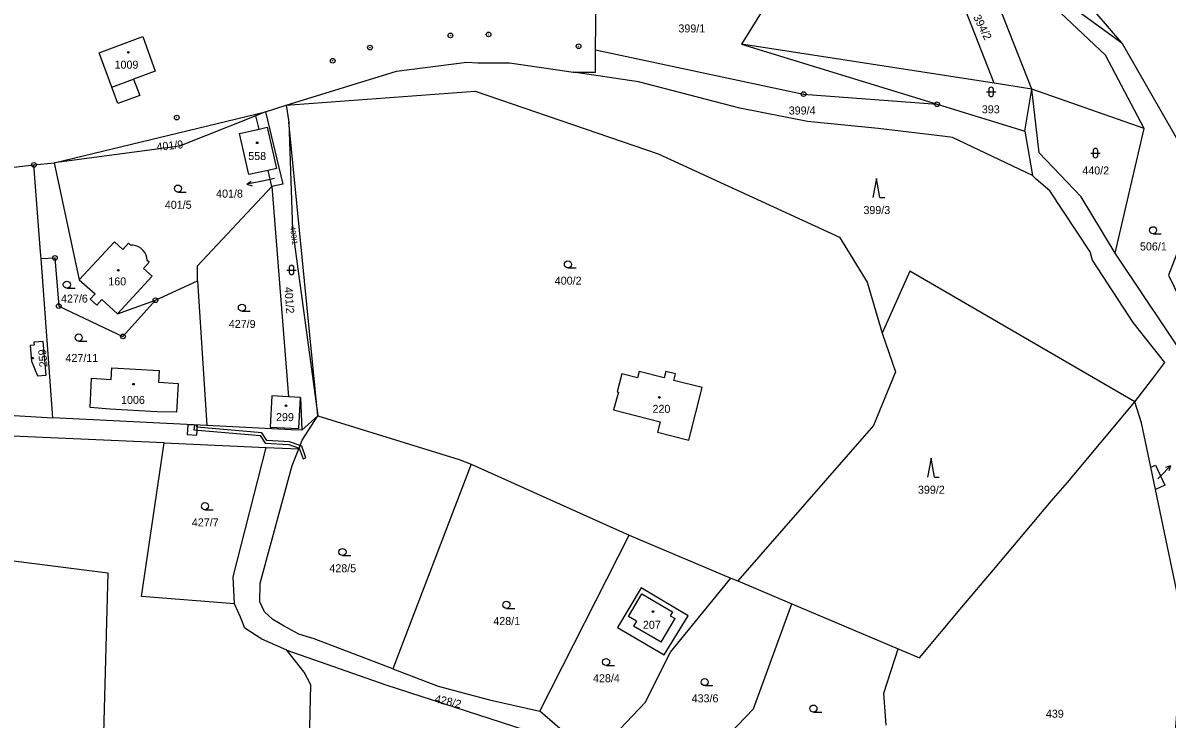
# Model space of a CAD drawing. Extents: x -725728 to -720881, y -1068679 to -1063504.
# Drawn here: x -723693.8 to -723450.7, y -1067427.1 to -1067279.2 of the extents above; entities that cross this region are included whole.
import ezdxf

# ---------------------------------------------------------------- set-up
doc = ezdxf.new("R2010")
doc.units = 0
for name, color, linetype in [('Hranice parcel', 7, 'Continuous'), ('Parcelní čísla', 7, 'Continuous'), ('Pop  PČ popisy', 7, 'Continuous'), ('Vnitřní kresba', 7, 'Continuous'), ('Věcná břemena k části', 7, 'Continuous'), ('Značky bodu BP', 7, 'Continuous'), ('Značky budov', 7, 'Continuous'), ('Značky kultur', 7, 'Continuous')]:
    doc.layers.add(name, color=color, linetype=linetype)

# ---------------------------------------------------------------- blocks, each defined once
blk = doc.blocks.new('4.02_4')
at = {"layer": 'Značky budov'}
blk.add_circle((-0.001, 0), 0.0175, dxfattribs=at)
blk = doc.blocks.new('4.02_3')
at = {"layer": 'Značky budov'}
blk.add_circle((-0.001, 0), 0.0175, dxfattribs=at)
blk = doc.blocks.new('1029_93')
at = {"layer": 'Pop  PČ popisy'}
for p, q in [((-0.293, -0.062), (-0.206, 0.007)), ((0, 0), (-0.293, -0.062)), ((-0.293, -0.062), (-0.185, -0.091))]:
    blk.add_line(p, q, dxfattribs=at)
blk = doc.blocks.new('1029_110')
at = {"layer": 'Pop  PČ popisy'}
for p, q in [((0, 0), (0.208, 0.216)), ((0.208, 0.216), (0.103, 0.179)), ((0.208, 0.216), (0.175, 0.109))]:
    blk.add_line(p, q, dxfattribs=at)
blk = doc.blocks.new('3.04_2')
at = {"layer": 'Značky kultur'}
blk.add_line((0.001, 0), (0.176, 0), dxfattribs=at)
blk.add_circle((0.001, 0.075), 0.075, dxfattribs=at)
blk = doc.blocks.new('3.16_2')
at = {"layer": 'Značky kultur'}
for p, q in [((-0.1, 0.1), (0.1, 0.1)), ((-0.05, 0.15), (-0.05, 0.05)), ((0.05, 0.05), (0.05, 0.15))]:
    blk.add_line(p, q, dxfattribs=at)
for centre, start, end in [((0, 0.15), 0, 180), ((0, 0.05), 180, 359.9879)]:
    blk.add_arc(centre, 0.05, start, end, dxfattribs=at)
blk = doc.blocks.new('3.04_3')
at = {"layer": 'Značky kultur'}
blk.add_line((0.001, 0), (0.176, 0), dxfattribs=at)
blk.add_circle((0.001, 0.075), 0.075, dxfattribs=at)
blk = doc.blocks.new('3.08_2')
at = {"layer": 'Značky kultur'}
for p, q in [((0, 0.4), (-0.075, 0)), ((0.075, 0), (0, 0.4)), ((0.075, 0), (0.175, 0))]:
    blk.add_line(p, q, dxfattribs=at)
blk = doc.blocks.new('3.08_1')
at = {"layer": 'Značky kultur'}
for p, q in [((0, 0.4), (-0.075, 0)), ((0.075, 0), (0, 0.4)), ((0.075, 0), (0.175, 0))]:
    blk.add_line(p, q, dxfattribs=at)
blk = doc.blocks.new('1.05_1')
at = {"layer": 'Značky bodu BP'}
for radius in [0.05, 0.00303]:
    blk.add_circle((0, 0), radius, dxfattribs=at)
blk = doc.blocks.new('1.05_2')
at = {"layer": 'Značky bodu BP'}
for radius in [0.05, 0.00303]:
    blk.add_circle((0, 0), radius, dxfattribs=at)

msp = doc.modelspace()

# ---------------------------------------------------------------- linework, layer by layer
at = {"layer": 'Hranice parcel'}
for p, q in [((-723572.12, -1067284.9), (-723571.84, -1067259.72)), ((-723460.32, -1067283.4), (-723469.08, -1067273.2)), ((-723536.24, -1067275.86), (-723541.11, -1067283.68)), ((-723541.11, -1067283.68), (-723499.61, -1067296.46)), ((-723487.5, -1067292), (-723541.11, -1067283.68)), ((-723479.48, -1067293.24), (-723487.5, -1067292)), ((-723480.98, -1067302.19), (-723479.48, -1067293.24)), ((-723455.59, -1067301.61), (-723479.48, -1067293.24)), ((-723642.24, -1067298.09), (-723637.82, -1067296.63)), ((-723637.82, -1067296.63), (-723637.28, -1067300.3)), ((-723499.61, -1067296.46), (-723480.98, -1067302.19)), ((-723687.12, -1067308.88), (-723642.24, -1067298.09)), ((-723642.24, -1067298.09), (-723644.27, -1067298.95)), ((-723643.59, -1067301.74), (-723644.27, -1067298.95)), ((-723631.1, -1067362.69), (-723637.28, -1067300.3)), ((-723480.98, -1067302.19), (-723479.34, -1067311.61)), ((-723461.74, -1067328.13), (-723455.59, -1067301.61)), ((-723691.4, -1067309.34), (-723687.12, -1067308.88)), ((-723687.12, -1067308.88), (-723681.82, -1067333.76)), ((-723640.9, -1067313.95), (-723641.66, -1067310.52)), ((-723640.9, -1067313.95), (-723637.32, -1067358.65)), ((-723436.8, -1067365.55), (-723461.74, -1067328.13)), ((-723687.41, -1067363.12), (-723689.89, -1067329.25)), ((-723665.61, -1067338.11), (-723656.68, -1067333.97)), ((-723656.68, -1067333.97), (-723654.7, -1067364.76)), ((-723673.63, -1067340.97), (-723665.61, -1067338.11)), ((-723634.8, -1067358.79), (-723637.32, -1067358.65)), ((-723634.8, -1067358.79), (-723634.54, -1067365.73)), ((-723722.85, -1067360.93), (-723687.41, -1067363.12)), ((-723634.54, -1067365.73), (-723631.1, -1067362.69)), ((-723663.72, -1067368.43), (-723739.93, -1067365.04)), ((-723654.7, -1067364.76), (-723687.41, -1067363.12)), ((-723663.72, -1067368.43), (-723642.12, -1067369.4)), ((-723642.12, -1067369.4), (-723635.16, -1067369.71)), ((-723598.56, -1067372.95), (-723615.22, -1067416.45)), ((-723598.56, -1067372.95), (-723564.97, -1067388.01)), ((-723453.2, -1067378.34), (-723454.19, -1067373.61)), ((-723564.97, -1067388.01), (-723543.39, -1067397.15)), ((-723543.39, -1067397.15), (-723541.92, -1067397.77)), ((-723541.92, -1067397.77), (-723530.41, -1067402.64)), ((-723530.41, -1067402.64), (-723507.89, -1067412.18))]:
    msp.add_line(p, q, dxfattribs=at)
for points in [[(-723487.5, -1067292), (-723497.56, -1067266.08), (-723536.73, -1067210.56)], [(-723479.48, -1067293.24), (-723487.12, -1067273.79), (-723514.57, -1067234.97)], [(-723455.59, -1067301.61), (-723463.81, -1067286.04), (-723487.72, -1067263.42), (-723460.32, -1067283.4)], [(-723668.3, -1067282.09), (-723665.63, -1067289.4), (-723670.25, -1067291.11), (-723668.94, -1067294.62), (-723673.58, -1067296.33), (-723674.88, -1067292.82), (-723677.57, -1067285.52), (-723668.3, -1067282.09)], [(-723576.81, -1067289.67), (-723572.17, -1067289.67), (-723572.12, -1067284.9)], [(-723572.12, -1067284.9), (-723527.95, -1067294.31), (-723499.61, -1067296.46)], [(-723460.32, -1067283.4), (-723448.73, -1067303.66), (-723446.82, -1067323.42), (-723450.44, -1067332.82), (-723436.73, -1067361.12)], [(-723637.82, -1067296.63), (-723614.4, -1067289.45), (-723599.47, -1067287.54), (-723597.13, -1067287.64), (-723590.42, -1067287.68), (-723576.81, -1067289.67)], [(-723479.34, -1067311.61), (-723496.32, -1067303.52), (-723497.9, -1067303.33), (-723512.09, -1067301.59), (-723527.14, -1067300.15), (-723541.47, -1067297.31), (-723563, -1067291.69), (-723576.81, -1067289.67)], [(-723637.82, -1067296.63), (-723597.68, -1067293.68), (-723558.82, -1067306.97), (-723520.35, -1067324.68), (-723514.45, -1067334.25), (-723511.25, -1067345.08)], [(-723461.74, -1067328.13), (-723468.99, -1067316.16), (-723477.92, -1067306.79), (-723479.48, -1067293.24)], [(-723644.27, -1067298.95), (-723660.48, -1067305.34), (-723687.12, -1067308.88)], [(-723642.24, -1067298.09), (-723638.52, -1067313.48), (-723640.9, -1067313.95)], [(-723641.66, -1067310.52), (-723645.78, -1067311.42), (-723647.75, -1067302.68), (-723643.59, -1067301.74)], [(-723643.59, -1067301.74), (-723641.9, -1067301.36), (-723639.88, -1067310.13), (-723641.66, -1067310.52)], [(-723637.28, -1067300.3), (-723636.49, -1067323.09), (-723631.1, -1067362.69)], [(-723722.57, -1067310.32), (-723701.77, -1067310.52), (-723691.4, -1067309.34)], [(-723689.89, -1067329.25), (-723690.05, -1067327.84), (-723691.4, -1067309.34)], [(-723457.62, -1067359.67), (-723453.37, -1067354.15), (-723451.23, -1067351.37), (-723457.92, -1067342.83), (-723466.6, -1067329.62), (-723467.11, -1067327.85), (-723475.62, -1067314.88), (-723478.54, -1067312.35), (-723479.34, -1067311.61)], [(-723656.68, -1067333.97), (-723656.67, -1067330.79), (-723640.9, -1067313.95)], [(-723670.92, -1067326.42), (-723671.36, -1067326.02), (-723672.55, -1067327.34), (-723674.33, -1067325.73), (-723681.82, -1067333.76)], [(-723667.36, -1067329.64), (-723667.44, -1067329.06), (-723667.61, -1067328.51), (-723667.88, -1067327.99), (-723668.23, -1067327.53), (-723668.3, -1067327.46), (-723668.73, -1067327.08), (-723669.23, -1067326.77), (-723669.77, -1067326.56), (-723670.34, -1067326.44), (-723670.92, -1067326.42)], [(-723689.89, -1067329.25), (-723686.96, -1067329.12), (-723686.15, -1067339.36), (-723672.5, -1067345.8), (-723665.61, -1067338.11)], [(-723673.63, -1067340.97), (-723666.31, -1067333), (-723668.11, -1067331.37), (-723666.91, -1067330.04), (-723667.36, -1067329.64)], [(-723681.82, -1067333.76), (-723678.41, -1067336.76), (-723679.45, -1067337.91), (-723678.08, -1067339.15), (-723677.02, -1067337.98), (-723673.63, -1067340.97)], [(-723457.62, -1067359.67), (-723505.41, -1067331.91), (-723511.25, -1067345.08)], [(-723511.25, -1067345.08), (-723508.46, -1067353.34), (-723513.12, -1067364.71), (-723541.92, -1067397.77)], [(-723691.4, -1067347.04), (-723691.34, -1067347.66), (-723692.24, -1067347.74), (-723691.94, -1067351.06), (-723690.67, -1067354.17), (-723688.83, -1067354.04), (-723689.46, -1067346.89), (-723691.4, -1067347.04)], [(-723674.99, -1067354.99), (-723674.84, -1067352.48), (-723664.83, -1067353.03), (-723664.96, -1067355.54), (-723660.81, -1067355.81), (-723661.14, -1067361.93), (-723665.29, -1067361.8), (-723675.32, -1067361.24), (-723679.5, -1067360.92), (-723679.17, -1067354.7), (-723674.99, -1067354.99)], [(-723567.57, -1067357.58), (-723567.28, -1067357.66), (-723568.31, -1067361.42), (-723558.42, -1067363.95), (-723558.98, -1067366.14), (-723552.31, -1067367.85), (-723549.46, -1067356.69), (-723555.5, -1067355.15), (-723555.15, -1067353.78), (-723557.19, -1067353.26), (-723557.54, -1067354.62), (-723562.87, -1067353.26), (-723563.21, -1067354.58), (-723566.52, -1067353.73), (-723567.57, -1067357.58)], [(-723637.32, -1067358.65), (-723640.92, -1067358.45), (-723641.26, -1067365.1), (-723636.79, -1067365.31), (-723635.13, -1067365.39), (-723634.8, -1067358.79)], [(-723507.89, -1067412.18), (-723503.33, -1067414.11), (-723494.32, -1067403.35), (-723487.59, -1067395.39), (-723480.86, -1067387.41), (-723475.38, -1067380.84), (-723471.91, -1067376.84), (-723457.62, -1067359.67)], [(-723454.19, -1067373.61), (-723456.17, -1067364.19), (-723457.62, -1067359.67)], [(-723635.16, -1067369.71), (-723634.41, -1067367.87), (-723631.1, -1067362.69)], [(-723631.1, -1067362.69), (-723601.09, -1067371.93), (-723598.56, -1067372.95)], [(-723634.54, -1067365.73), (-723636.76, -1067365.62), (-723654.7, -1067364.76)], [(-723648.85, -1067402.64), (-723668.56, -1067401.06), (-723663.72, -1067368.43)], [(-723648.85, -1067402.64), (-723649.12, -1067396.88), (-723642.12, -1067369.4)], [(-723615.22, -1067416.45), (-723631.91, -1067410.07), (-723635.15, -1067409.05), (-723638.24, -1067407.35), (-723640.67, -1067405.93), (-723642.41, -1067404.36), (-723643.44, -1067402.22), (-723643.34, -1067398.27), (-723636.59, -1067373.23), (-723635.16, -1067369.71)], [(-723454.19, -1067373.61), (-723453.23, -1067373.15), (-723451.24, -1067377.41), (-723453.2, -1067378.34)], [(-723450.18, -1067474.94), (-723451.44, -1067461.37), (-723447.16, -1067407.06), (-723453.2, -1067378.34)], [(-723740.9, -1067387.76), (-723675.74, -1067396.06), (-723677.11, -1067448.62), (-723709.18, -1067438.04), (-723714.12, -1067429.85), (-723746.27, -1067428.34)], [(-723583.96, -1067425.46), (-723583.89, -1067425.31), (-723564.97, -1067388.01)], [(-723573.44, -1067442.03), (-723566.89, -1067429.21), (-723561.56, -1067423.59), (-723556.22, -1067412.91), (-723543.39, -1067397.15)], [(-723562.43, -1067399.23), (-723567.48, -1067407.67), (-723557.58, -1067413.49), (-723552.44, -1067405.15), (-723562.43, -1067399.23)], [(-723637.69, -1067412.51), (-723643.02, -1067410.13), (-723646.59, -1067407.79), (-723647.55, -1067405.44), (-723648.85, -1067402.64)], [(-723548.77, -1067435.6), (-723538.57, -1067424.94), (-723530.41, -1067402.64)], [(-723630.98, -1067482.06), (-723633.44, -1067455.65), (-723632.6, -1067419.83), (-723634.04, -1067417.13), (-723637.69, -1067412.51)], [(-723637.69, -1067412.51), (-723616.67, -1067419.83), (-723584.74, -1067430.22), (-723579.59, -1067434.58), (-723577.76, -1067437.55), (-723577.73, -1067441.73), (-723578.76, -1067445.97), (-723585.22, -1067454.59), (-723601.06, -1067467.91), (-723630.59, -1067486.22)], [(-723510.44, -1067428.44), (-723510.92, -1067421.64), (-723507.89, -1067412.18)], [(-723615.22, -1067416.45), (-723605.56, -1067420.14), (-723594.63, -1067423.01), (-723583.96, -1067425.46)], [(-723573.44, -1067442.03), (-723573.49, -1067438.05), (-723574.95, -1067434.36), (-723576.89, -1067431.35), (-723579.7, -1067429.12), (-723583.96, -1067425.46)]]:
    msp.add_lwpolyline(points, dxfattribs=at)
at = {"layer": 'Pop  PČ popisy'}
for p, q in [((-723640.29, -1067312.25), (-723643.24, -1067312.86)), ((-723452.68, -1067376.06), (-723452.12, -1067375.48))]:
    msp.add_line(p, q, dxfattribs=at)
at = {"layer": 'Vnitřní kresba'}
for p, q in [((-723674.88, -1067292.82), (-723670.25, -1067291.11)), ((-723565.14, -1067405.34), (-723562.33, -1067400.49)), ((-723562.33, -1067400.49), (-723555.78, -1067404.3)), ((-723563.46, -1067406.32), (-723565.14, -1067405.34)), ((-723563.46, -1067406.32), (-723564.06, -1067407.36)), ((-723558.18, -1067410.78), (-723555.25, -1067405.73)), ((-723555.78, -1067404.3), (-723556.28, -1067405.17)), ((-723556.28, -1067405.17), (-723555.25, -1067405.73)), ((-723558.18, -1067410.78), (-723564.06, -1067407.36))]:
    msp.add_line(p, q, dxfattribs=at)
at = {"layer": 'Věcná břemena k části'}
for points in [[(-723658.86, -1067366.67), (-723656.84, -1067366.81), (-723656.68, -1067364.66), (-723658.7, -1067364.56)], [(-723656.87, -1067364.65), (-723657.3, -1067364.63), (-723657.47, -1067365.65), (-723643.33, -1067366.84), (-723642.28, -1067368.5), (-723637.26, -1067368.76), (-723635.09, -1067369.54), (-723634.86, -1067368.99), (-723637.14, -1067368.17), (-723641.94, -1067367.92), (-723642.98, -1067366.27), (-723656.85, -1067365.1)], [(-723635.09, -1067369.54), (-723634.26, -1067371.81), (-723633.69, -1067371.63), (-723634.49, -1067369.12), (-723634.86, -1067368.99)]]:
    msp.add_lwpolyline(points, close=True, dxfattribs=at)

# ---------------------------------------------------------------- block references
at = {"layer": 'Pop  PČ popisy', "xscale": 10, "yscale": 10}
for name, p in [('1029_93', (-723643.24, -1067312.86)), ('1029_110', (-723452.12, -1067375.48))]:
    msp.add_blockref(name, p, dxfattribs=at)
at = {"layer": 'Značky bodu BP', "xscale": 10, "yscale": 10}
for name, p in [('1.05_1', (-723602.95, -1067281.83)), ('1.05_2', (-723594.84, -1067281.64)), ('1.05_2', (-723620.04, -1067284.43)), ('1.05_2', (-723575.73, -1067284.13)), ('1.05_1', (-723627.95, -1067287.21)), ('1.05_1', (-723527.95, -1067294.31)), ('1.05_1', (-723499.61, -1067296.46)), ('1.05_1', (-723661.08, -1067299.28)), ('1.05_1', (-723691.4, -1067309.34)), ('1.05_1', (-723686.96, -1067329.12)), ('1.05_1', (-723665.61, -1067338.11)), ('1.05_1', (-723686.15, -1067339.36)), ('1.05_1', (-723672.5, -1067345.8))]:
    msp.add_blockref(name, p, dxfattribs=at)
at = {"layer": 'Značky budov', "xscale": 10, "yscale": 10}
for name, p in [('4.02_4', (-723671.35, -1067285.42)), ('4.02_4', (-723643.99, -1067304.65)), ('4.02_3', (-723673.47, -1067331.74)), ('4.02_4', (-723691.67, -1067350.4)), ('4.02_3', (-723670.27, -1067355.95)), ('4.02_3', (-723637.85, -1067360.54)), ('4.02_3', (-723558.58, -1067358.77)), ('4.02_3', (-723559.91, -1067404.27))]:
    msp.add_blockref(name, p, dxfattribs=at)
at = {"layer": 'Značky kultur', "xscale": 10, "yscale": 10}
for name, p in [('3.16_2', (-723488.11, -1067294.84)), ('3.16_2', (-723465.97, -1067307.84)), ('3.04_3', (-723660.84, -1067315.13)), ('3.08_1', (-723512.47, -1067316.25)), ('3.04_2', (-723453.73, -1067323.98)), ('3.16_2', (-723636.69, -1067332.69)), ('3.04_2', (-723578.02, -1067331.25)), ('3.04_2', (-723684.43, -1067335.56)), ('3.04_2', (-723647.25, -1067340.45)), ('3.04_2', (-723681.93, -1067346.78)), ('3.08_2', (-723500.88, -1067375.68)), ('3.04_2', (-723655.1, -1067382.62)), ('3.04_2', (-723625.89, -1067392.37)), ('3.04_2', (-723591.07, -1067403.59)), ('3.04_2', (-723569.9, -1067415.74)), ('3.04_2', (-723548.95, -1067420.01)), ('3.04_3', (-723525.86, -1067425.64))]:
    msp.add_blockref(name, p, dxfattribs=at)

# ---------------------------------------------------------------- texts
at = {"layer": 'Parcelní čísla'}
for s, height, rotation, p in [('394/2', 1.7, 297, (-723491.99, -1067277.94)), ('401/9', 1.7, 6, (-723665.28, -1067306.38)), ('400/1', 1.14, 278, (-723637.05, -1067322.48)), ('401/2', 1.7, 274, (-723638.19, -1067335.34)), ('259', 1.7, 95, (-723688.52, -1067352.25)), ('428/2', 1.7, 347, (-723606.41, -1067423.55))]:
    msp.add_text(s, height=height, rotation=rotation, dxfattribs=at).set_placement(p)
for s, p in [('399/1', (-723554.53, -1067281.2)), ('1009', (-723674.29, -1067288.9)), ('399/4', (-723531.1, -1067298.64)), ('393', (-723490.08, -1067298.39)), ('558', (-723645.89, -1067308.32)), ('440/2', (-723468.74, -1067311.39)), ('401/8', (-723652.72, -1067316.3)), ('401/5', (-723663.61, -1067318.68)), ('399/3', (-723515.24, -1067319.8)), ('506/1', (-723456.5, -1067327.53)), ('160', (-723675.61, -1067334.96)), ('400/2', (-723580.79, -1067334.8)), ('427/6', (-723685.66, -1067338.61)), ('427/9', (-723650.02, -1067344)), ('427/11', (-723684.71, -1067351.24)), ('1006', (-723672.91, -1067360.15)), ('220', (-723560.03, -1067362.04)), ('299', (-723640, -1067363.8)), ('399/2', (-723503.65, -1067379.23)), ('427/7', (-723657.87, -1067386.17)), ('428/5', (-723628.66, -1067395.92)), ('428/1', (-723593.84, -1067407.14)), ('207', (-723562.07, -1067407.94)), ('428/4', (-723572.67, -1067419.29)), ('433/6', (-723551.72, -1067423.56)), ('439', (-723476.48, -1067426.84))]:
    msp.add_text(s, height=1.7, dxfattribs=at).set_placement(p)

doc.saveas('drawing.dxf')
